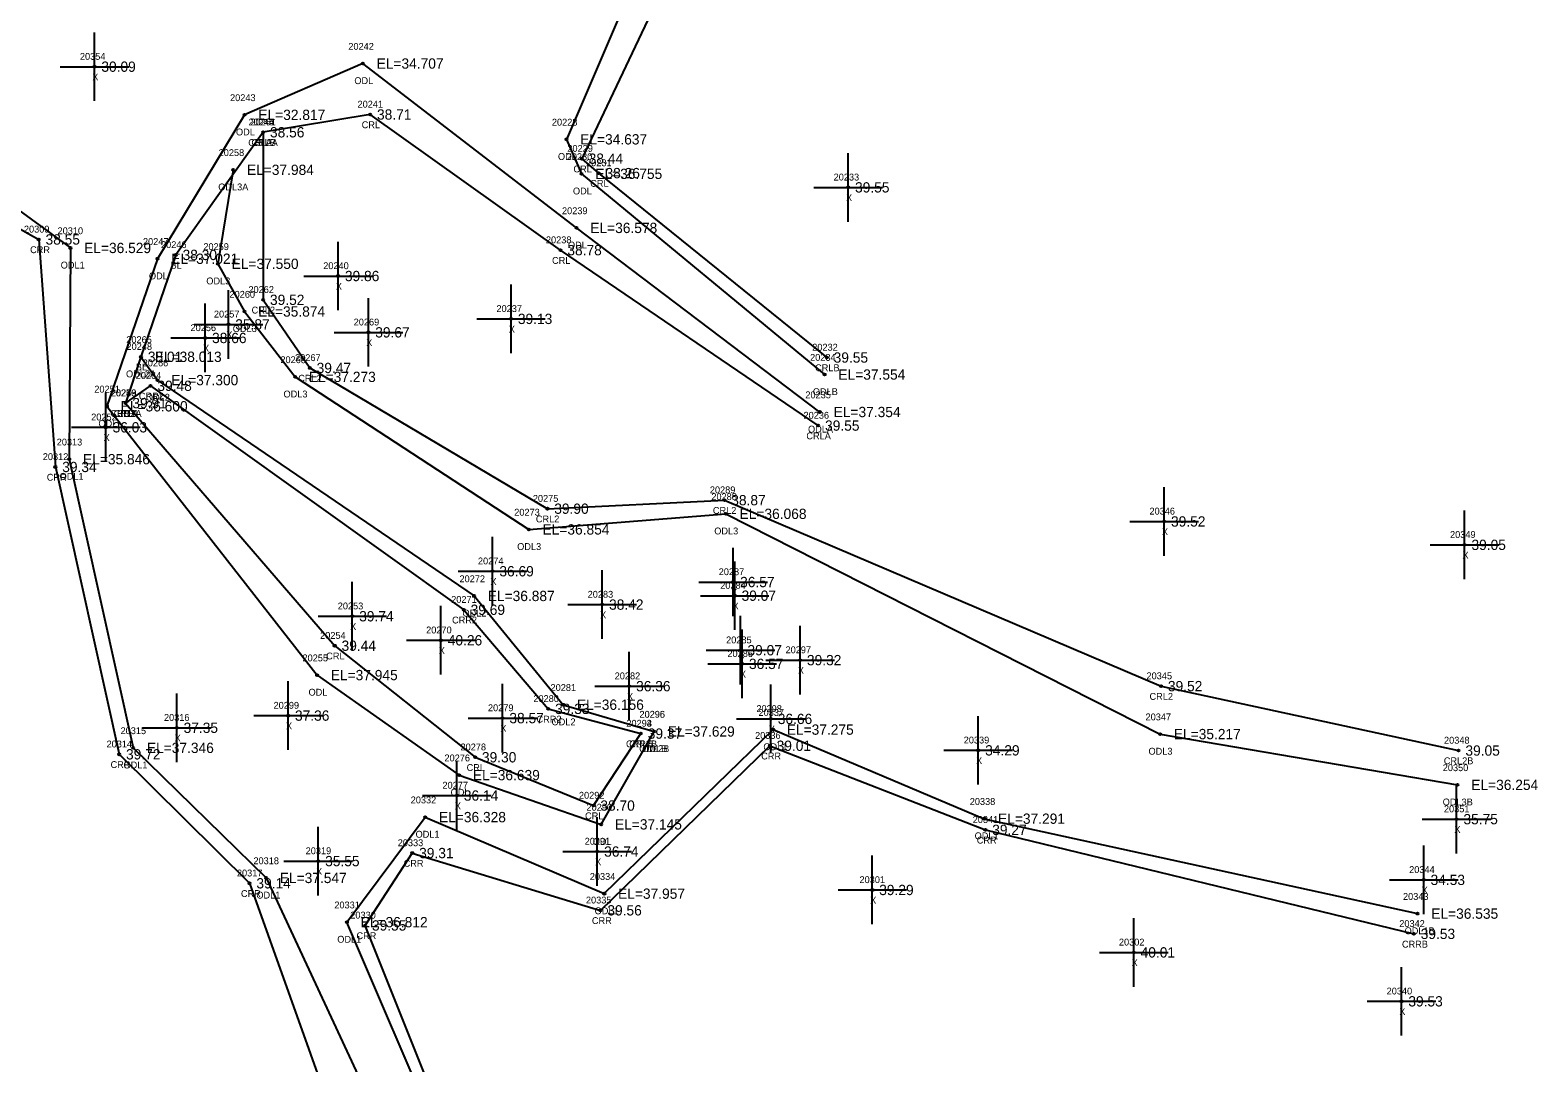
# Model space of a CAD drawing. Extents: x 2619569 to 2620117, y 784503 to 785150.
# Drawn here: x 2619897.7 to 2620117.4, y 784673.4 to 784823.9 of the extents above; entities that cross this region are included whole.
import ezdxf

# ---------------------------------------------------------------- set-up
doc = ezdxf.new("R2010")
doc.units = 0
for name, color, linetype in [('RD_DTM_BkLn1', 7, 'Continuous'), ('RD_DTM_BkLn_txCode', 7, 'Continuous'), ('RD_EX_H2O', 7, 'Continuous'), ('RD_EX_H2O_txCode', 7, 'Continuous'), ('RD_EX_Misc', 7, 'Continuous'), ('RD_EX_Misc_txCode', 7, 'Continuous'), ('RD_EX_TX_H2O_ELEV', 7, 'Continuous'), ('RD_EX_TX_Misc_ELEV', 7, 'Continuous'), ('RD_SMD_Locator', 7, 'Continuous')]:
    doc.layers.add(name, color=color, linetype=linetype)

msp = doc.modelspace()

# ---------------------------------------------------------------- linework, layer by layer
at = {"layer": 'RD_DTM_BkLn1'}
msp.add_lwpolyline([(2619931.64, 784808.99), (2619918.9, 784791.11), (2619913.84, 784776.27), (2619911.58, 784769.51)], dxfattribs=at)
at = {"layer": 'RD_EX_H2O'}
for points in [[(2619849.21, 784838.05), (2619855.06, 784843.73), (2619862.98, 784854.68), (2619876.77, 784858.94), (2619905.89, 784860.53), (2619923.25, 784863.85), (2619948.05, 784872.76), (2619969.08, 784848.67), (2619985.64, 784830.75), (2619975.85, 784807.96), (2619978.05, 784802.93), (2620013.48, 784773.68)], [(2619850.74, 784850.04), (2619858.56, 784858.85), (2619863.71, 784859.84), (2619875.95, 784863.3), (2619903.67, 784868.12), (2619924.46, 784867.36), (2619949.26, 784874.61), (2619971.3, 784850.55), (2619990.94, 784832.2), (2619978.09, 784805.14), (2619980.54, 784803.04), (2620013.79, 784776.16)], [(2620012.79, 784768.22), (2619977.32, 784795.05), (2619946.18, 784819.01), (2619928.94, 784811.53), (2619916.25, 784790.56), (2619908.88, 784769.05), (2619939.5, 784729.88), (2619960.21, 784715.3), (2619980.92, 784708.12), (2619988.62, 784721.66)], [(2619851.94, 784812.36), (2619867.47, 784809.26), (2619885.8, 784805.06), (2619903.55, 784792.13), (2619903.39, 784761.34), (2619912.7, 784719.27), (2619932.07, 784700.31), (2619950.07, 784661.69), (2619964.86, 784626.79)], [(2620012.54, 784766.24), (2619974.98, 784791.81), (2619947.24, 784811.58), (2619931.64, 784808.99)], [(2619931.64, 784808.99), (2619931.64, 784784.57), (2619938.44, 784774.64), (2619973.07, 784754.13), (2619998.87, 784755.37), (2620062.51, 784728.27), (2620105.87, 784718.88)], [(2619858.79, 784802.44), (2619861.97, 784802.62), (2619885.46, 784800.96), (2619898.93, 784793.37), (2619901.36, 784760.21), (2619910.66, 784718.33), (2619929.66, 784699.53), (2619944.47, 784658), (2619963.48, 784625.35)], [(2619927.28, 784803.52), (2619925.05, 784789.82), (2619928.92, 784782.87), (2619936.3, 784773.34), (2619970.36, 784751.11), (2619999.08, 784753.38), (2620062.37, 784721.28), (2620105.72, 784713.88)], [(2619913.84, 784776.27), (2619916.26, 784772.87), (2619962.38, 784741.41), (2619975.37, 784725.56), (2619988.62, 784721.66)], [(2619911.58, 784769.51), (2619915.23, 784772.04), (2619960.88, 784739.4), (2619973.19, 784724.95), (2619986.7, 784721.35)], [(2619911.58, 784769.51), (2619942.07, 784734.16), (2619962.53, 784717.9), (2619979.79, 784710.86), (2619986.7, 784721.35)], [(2619970.99, 784633.29), (2619957.32, 784662.49), (2619943.86, 784693.87), (2619955.27, 784709.18), (2619981.37, 784698.02), (2620005.96, 784721.93), (2620036.75, 784708.95), (2620099.89, 784695.11)], [(2619972.95, 784635.56), (2619958.84, 784662.55), (2619946.5, 784693.39), (2619953.38, 784703.94), (2619980.81, 784695.59), (2620005.48, 784719.58), (2620036.9, 784707.32), (2620099.35, 784692.16)]]:
    msp.add_lwpolyline(points, dxfattribs=at)
at = {"layer": 'RD_EX_Misc'}
for p, q in [((2619907.06, 784813.55), (2619907.06, 784823.55)), ((2619902.06, 784818.55), (2619912.06, 784818.55)), ((2620016.91, 784795.96), (2620016.91, 784805.96)), ((2620011.91, 784800.96), (2620021.91, 784800.96)), ((2619942.56, 784783.04), (2619942.56, 784793.04)), ((2619937.56, 784788.04), (2619947.56, 784788.04)), ((2619967.77, 784776.79), (2619967.77, 784786.79)), ((2619926.58, 784775.99), (2619926.58, 784785.99)), ((2619946.98, 784774.83), (2619946.98, 784784.83)), ((2619923.2, 784774.01), (2619923.2, 784784.01)), ((2619921.58, 784780.99), (2619931.58, 784780.99)), ((2619962.77, 784781.79), (2619972.77, 784781.79)), ((2619918.2, 784779.01), (2619928.2, 784779.01)), ((2619941.98, 784779.83), (2619951.98, 784779.83)), ((2619908.7, 784760.99), (2619908.7, 784770.99)), ((2619903.7, 784765.99), (2619913.7, 784765.99)), ((2620062.96, 784747.27), (2620062.96, 784757.27)), ((2620106.75, 784743.86), (2620106.75, 784753.86)), ((2620057.96, 784752.27), (2620067.96, 784752.27)), ((2619965.07, 784740.01), (2619965.07, 784750.01)), ((2620000.16, 784738.44), (2620000.16, 784748.44)), ((2620101.75, 784748.86), (2620111.75, 784748.86)), ((2619960.07, 784745.01), (2619970.07, 784745.01)), ((2619981.06, 784735.15), (2619981.06, 784745.15)), ((2620000.37, 784736.45), (2620000.37, 784746.45)), ((2619944.64, 784733.45), (2619944.64, 784743.45)), ((2619995.16, 784743.44), (2620005.16, 784743.44)), ((2619995.37, 784741.45), (2620005.37, 784741.45)), ((2619939.64, 784738.45), (2619949.64, 784738.45)), ((2619957.55, 784729.95), (2619957.55, 784739.95)), ((2619976.06, 784740.15), (2619986.06, 784740.15)), ((2620001.23, 784728.5), (2620001.23, 784738.5)), ((2620001.45, 784726.51), (2620001.45, 784736.51)), ((2620009.9, 784727.06), (2620009.9, 784737.06)), ((2619952.55, 784734.95), (2619962.55, 784734.95)), ((2619985, 784723.26), (2619985, 784733.26)), ((2619996.23, 784733.5), (2620006.23, 784733.5)), ((2620004.9, 784732.06), (2620014.9, 784732.06)), ((2619996.45, 784731.51), (2620006.45, 784731.51)), ((2619935.28, 784718.97), (2619935.28, 784728.97)), ((2619966.53, 784718.61), (2619966.53, 784728.61)), ((2619980, 784728.26), (2619990, 784728.26)), ((2620005.65, 784718.49), (2620005.65, 784728.49)), ((2619919.05, 784717.2), (2619919.05, 784727.2)), ((2619930.28, 784723.97), (2619940.28, 784723.97)), ((2619961.53, 784723.61), (2619971.53, 784723.61)), ((2620000.65, 784723.49), (2620010.65, 784723.49)), ((2620035.87, 784713.91), (2620035.87, 784723.91)), ((2619914.05, 784722.2), (2619924.05, 784722.2)), ((2620030.87, 784718.91), (2620040.87, 784718.91)), ((2619959.89, 784707.32), (2619959.89, 784717.32)), ((2619954.89, 784712.32), (2619964.89, 784712.32)), ((2620105.58, 784703.88), (2620105.58, 784713.88)), ((2619939.68, 784697.77), (2619939.68, 784707.77)), ((2619980.34, 784699.16), (2619980.34, 784709.16)), ((2620100.58, 784708.88), (2620110.58, 784708.88)), ((2619975.34, 784704.16), (2619985.34, 784704.16)), ((2620020.43, 784693.56), (2620020.43, 784703.56)), ((2620100.79, 784695.03), (2620100.79, 784705.03)), ((2619934.68, 784702.77), (2619944.68, 784702.77)), ((2620095.79, 784700.03), (2620105.79, 784700.03)), ((2620015.43, 784698.56), (2620025.43, 784698.56)), ((2620058.53, 784684.46), (2620058.53, 784694.46)), ((2620053.53, 784689.46), (2620063.53, 784689.46)), ((2620097.55, 784677.33), (2620097.55, 784687.33)), ((2620092.55, 784682.33), (2620102.55, 784682.33))]:
    msp.add_line(p, q, dxfattribs=at)
at = {"layer": 'RD_SMD_Locator'}
for centre in [(2619907.06, 784818.55), (2619946.18, 784819.01), (2619928.94, 784811.53), (2619947.24, 784811.58), (2619931.64, 784808.99), (2619931.64, 784808.99), (2619931.64, 784808.99), (2619975.85, 784807.96), (2619978.09, 784805.14), (2619927.28, 784803.52), (2619978.05, 784802.93), (2619980.54, 784803.04), (2620016.91, 784800.96), (2619898.93, 784793.37), (2619977.32, 784795.05), (2619903.55, 784792.13), (2619918.9, 784791.11), (2619974.98, 784791.81), (2619916.25, 784790.56), (2619925.05, 784789.82), (2619942.56, 784788.04), (2619931.64, 784784.57), (2619928.92, 784782.87), (2619926.58, 784780.99), (2619967.77, 784781.79), (2619923.2, 784779.01), (2619946.98, 784779.83), (2619913.84, 784776.27), (2619913.84, 784776.27), (2620013.79, 784776.16), (2619938.44, 784774.64), (2620013.48, 784773.68), (2619915.23, 784772.04), (2619916.26, 784772.87), (2619936.3, 784773.34), (2619908.88, 784769.05), (2619911.58, 784769.51), (2619911.58, 784769.51), (2619911.58, 784769.51), (2620012.79, 784768.22), (2619908.7, 784765.99), (2620012.54, 784766.24), (2619901.36, 784760.21), (2619903.39, 784761.34), (2619973.07, 784754.13), (2619998.87, 784755.37), (2619999.08, 784753.38), (2620062.96, 784752.27), (2619970.36, 784751.11), (2620106.75, 784748.86), (2619965.07, 784745.01), (2620000.16, 784743.44), (2619962.38, 784741.41), (2620000.37, 784741.45), (2619944.64, 784738.45), (2619960.88, 784739.4), (2619981.06, 784740.15), (2619942.07, 784734.16), (2619957.55, 784734.95), (2620001.23, 784733.5), (2620009.9, 784732.06), (2619939.5, 784729.88), (2620001.45, 784731.51), (2619985, 784728.26), (2620062.51, 784728.27), (2619975.37, 784725.56), (2619935.28, 784723.97), (2619966.53, 784723.61), (2619973.19, 784724.95), (2620005.65, 784723.49), (2619919.05, 784722.2), (2619986.7, 784721.35), (2619986.7, 784721.35), (2619988.62, 784721.66), (2619988.62, 784721.66), (2620005.96, 784721.93), (2620062.37, 784721.28), (2619912.7, 784719.27), (2620005.48, 784719.58), (2620035.87, 784718.91), (2620105.87, 784718.88), (2619910.66, 784718.33), (2619962.53, 784717.9), (2619960.21, 784715.3), (2619959.89, 784712.32), (2620105.72, 784713.88), (2619979.79, 784710.86), (2619955.27, 784709.18), (2619980.92, 784708.12), (2620036.75, 784708.95), (2620105.58, 784708.88), (2620036.9, 784707.32), (2619953.38, 784703.94), (2619980.34, 784704.16), (2619939.68, 784702.77), (2619929.66, 784699.53), (2619932.07, 784700.31), (2620100.79, 784700.03), (2619981.37, 784698.02), (2620020.43, 784698.56), (2619980.81, 784695.59), (2620099.89, 784695.11), (2619943.86, 784693.87), (2619946.5, 784693.39), (2620099.35, 784692.16), (2620058.53, 784689.46), (2620097.55, 784682.33)]:
    msp.add_circle(centre, 0.15, dxfattribs=at)

# ---------------------------------------------------------------- texts
at = {"layer": 'RD_DTM_BkLn_txCode'}
for s, p in [('20245', (2619929.52, 784809.99)), ('BLA', (2619930.4, 784806.99)), ('20246', (2619916.76, 784792.11)), ('BL', (2619918.15, 784789.11)), ('20248', (2619911.73, 784777.27)), ('BL', (2619913.09, 784774.27)), ('20250', (2619909.42, 784770.51)), ('BLB', (2619910.35, 784767.51))]:
    msp.add_text(s, height=1, dxfattribs=at).set_placement(p)
at = {"layer": 'RD_EX_H2O_txCode'}
for s, p in [('20242', (2619944.06, 784821.01)), ('ODL', (2619944.94, 784816.01)), ('20243', (2619926.82, 784813.53)), ('20241', (2619945.4, 784812.58)), ('20244', (2619929.52, 784809.99)), ('20261', (2619929.78, 784809.99)), ('20228', (2619973.73, 784809.96)), ('ODL', (2619927.69, 784808.53)), ('CRL', (2619946.01, 784809.58)), ('20258', (2619925.16, 784805.52)), ('CRL2A', (2619929.47, 784806.99)), ('CRLB', (2619929.94, 784806.99)), ('20229', (2619975.98, 784806.14)), ('ODL', (2619974.61, 784804.96)), ('20230', (2619975.89, 784804.93)), ('20231', (2619978.71, 784804.04)), ('CRL', (2619976.87, 784803.14)), ('ODL3A', (2619925.1, 784800.52)), ('ODL', (2619976.8, 784799.93)), ('CRL', (2619979.32, 784801.04)), ('20239', (2619975.2, 784797.05)), ('20309', (2619896.78, 784794.37)), ('20310', (2619901.68, 784794.13)), ('20247', (2619914.13, 784792.56)), ('20238', (2619972.86, 784792.81)), ('CRR', (2619897.68, 784791.37)), ('20259', (2619922.93, 784791.82)), ('ODL', (2619976.07, 784792.05)), ('ODL1', (2619902.14, 784789.13)), ('CRL', (2619973.75, 784789.81)), ('ODL', (2619915, 784787.56)), ('ODL3', (2619923.36, 784786.82)), ('20260', (2619926.74, 784784.87)), ('20262', (2619929.5, 784785.57)), ('CRL2', (2619929.96, 784782.57)), ('ODL3', (2619927.22, 784779.87)), ('20265', (2619911.7, 784778.27)), ('20232', (2620011.67, 784777.16)), ('20266', (2619914.09, 784774.87)), ('20268', (2619934.16, 784775.34)), ('20267', (2619936.3, 784775.64)), ('20234', (2620011.36, 784775.68)), ('ODL2A', (2619911.66, 784773.27)), ('20264', (2619913.08, 784773.04)), ('CRL2', (2619936.76, 784772.64)), ('CRLB', (2620012.09, 784774.16)), ('20251', (2619907.04, 784771.05)), ('20263', (2619909.44, 784770.51)), ('20249', (2619909.46, 784770.51)), ('ODL3', (2619934.61, 784770.34)), ('ODLB', (2620011.76, 784770.68)), ('CRR2', (2619913.53, 784770.04)), ('ODL2', (2619914.56, 784769.87)), ('20235', (2620010.67, 784770.22)), ('ODL', (2619907.64, 784766.05)), ('CRR2A', (2619909.39, 784767.51)), ('CRLA', (2619909.86, 784767.51)), ('20236', (2620010.4, 784767.24)), ('CRLA', (2620010.82, 784764.24)), ('ODLA', (2620011.06, 784765.22)), ('20313', (2619901.56, 784763.34)), ('20312', (2619899.53, 784761.21)), ('CRR', (2619900.11, 784758.21)), ('ODL1', (2619901.98, 784758.34)), ('20275', (2619970.95, 784755.13)), ('20289', (2619996.75, 784756.37)), ('20288', (2619996.97, 784755.38)), ('20273', (2619968.24, 784753.11)), ('CRL2', (2619997.19, 784753.37)), ('CRL2', (2619971.39, 784752.13)), ('ODL3', (2619997.39, 784750.38)), ('ODL3', (2619968.67, 784748.11)), ('20272', (2619960.26, 784743.41)), ('20271', (2619959.05, 784740.4)), ('CRR2', (2619959.18, 784737.4)), ('ODL2', (2619960.69, 784738.41)), ('20254', (2619939.95, 784735.16)), ('20255', (2619937.38, 784731.88)), ('CRL', (2619940.84, 784732.16)), ('20345', (2620060.39, 784729.27)), ('ODL', (2619938.26, 784726.88)), ('20281', (2619973.53, 784727.56)), ('20280', (2619971.03, 784725.95)), ('CRL2', (2620060.83, 784726.27)), ('CRR2', (2619971.49, 784722.95)), ('ODL2', (2619973.68, 784722.56)), ('20293', (2619984.58, 784722.35)), ('20294', (2619984.58, 784722.35)), ('20296', (2619986.48, 784723.66)), ('20295', (2619986.5, 784723.66)), ('20337', (2620003.84, 784723.93)), ('20347', (2620060.25, 784723.28)), ('20315', (2619910.86, 784721.27)), ('20336', (2620003.34, 784720.58)), ('20348', (2620103.75, 784719.88)), ('20314', (2619908.82, 784719.33)), ('20278', (2619960.41, 784718.9)), ('CRR2B', (2619984.53, 784719.35)), ('CRLB', (2619985, 784719.35)), ('ODL2B', (2619986.45, 784718.66)), ('ODLB', (2619986.9, 784718.66)), ('ODL1', (2620004.55, 784718.93)), ('ODL3', (2620060.68, 784718.28)), ('CRR', (2619909.41, 784716.33)), ('ODL1', (2619911.29, 784716.27)), ('20276', (2619958.07, 784717.3)), ('CRL', (2619961.3, 784715.9)), ('CRR', (2620004.23, 784717.58)), ('20350', (2620103.57, 784715.88)), ('CRL2B', (2620103.72, 784716.88)), ('20332', (2619953.15, 784711.18)), ('ODL', (2619958.97, 784712.3)), ('20292', (2619977.67, 784711.86)), ('CRL', (2619978.56, 784708.86)), ('20290', (2619978.77, 784710.12)), ('20338', (2620034.63, 784710.95)), ('ODL3B', (2620103.56, 784710.88)), ('20341', (2620035.06, 784708.32)), ('20333', (2619951.26, 784704.94)), ('ODL1', (2619953.86, 784706.18)), ('ODL', (2619979.68, 784705.12)), ('ODL1', (2620035.34, 784705.95)), ('CRR', (2620035.65, 784705.32)), ('20318', (2619930.23, 784702.31)), ('20317', (2619927.82, 784700.53)), ('CRR', (2619952.12, 784701.94)), ('20334', (2619979.25, 784700.02)), ('CRR', (2619928.41, 784697.53)), ('ODL1', (2619930.66, 784697.31)), ('20331', (2619942.02, 784695.87)), ('20335', (2619978.69, 784696.59)), ('20343', (2620097.77, 784697.11)), ('20330', (2619944.34, 784694.39)), ('CRR', (2619979.56, 784693.59)), ('ODL1', (2619979.96, 784695.02)), ('CRR', (2619945.25, 784691.39)), ('20342', (2620097.23, 784693.16)), ('ODL1B', (2620098.01, 784692.11)), ('ODL1', (2619942.45, 784690.87)), ('CRRB', (2620097.62, 784690.16))]:
    msp.add_text(s, height=1, dxfattribs=at).set_placement(p)
at = {"layer": 'RD_EX_Misc_txCode'}
for s, p in [('20354', (2619904.94, 784819.55)), ('X', (2619906.74, 784816.55)), ('20233', (2620014.79, 784801.96)), ('X', (2620016.6, 784798.96)), ('20240', (2619940.4, 784789.04)), ('X', (2619942.24, 784786.04)), ('20257', (2619924.47, 784781.99)), ('20237', (2619965.65, 784782.79)), ('20256', (2619921.06, 784780.01)), ('20269', (2619944.84, 784780.83)), ('X', (2619967.45, 784779.79)), ('X', (2619922.88, 784777.01)), ('X', (2619926.27, 784778.99)), ('X', (2619946.67, 784777.83)), ('20252', (2619906.58, 784766.99)), ('X', (2619908.39, 784763.99)), ('20346', (2620060.82, 784753.27)), ('X', (2620062.64, 784750.27)), ('20349', (2620104.63, 784749.86)), ('X', (2620106.44, 784746.86)), ('20274', (2619962.95, 784746.01)), ('20287', (2619998.04, 784744.44)), ('X', (2619964.76, 784743.01)), ('20284', (2619998.26, 784742.45)), ('20283', (2619978.94, 784741.15)), ('X', (2619999.84, 784741.44)), ('20253', (2619942.52, 784739.45)), ('X', (2619980.75, 784738.15)), ('X', (2620000.06, 784739.45)), ('X', (2619944.32, 784736.45)), ('20270', (2619955.4, 784735.95)), ('20285', (2619999.12, 784734.5)), ('20297', (2620007.78, 784733.06)), ('X', (2619957.24, 784732.95)), ('20286', (2619999.31, 784732.51)), ('X', (2620000.92, 784731.5)), ('20282', (2619982.88, 784729.26)), ('X', (2620001.13, 784729.51)), ('X', (2620009.58, 784730.06)), ('20299', (2619933.16, 784724.97)), ('20279', (2619964.41, 784724.61)), ('X', (2619984.68, 784726.26)), ('20298', (2620003.53, 784724.49)), ('20316', (2619917.19, 784723.2)), ('X', (2619918.74, 784720.2)), ('X', (2619934.97, 784721.97)), ('X', (2619966.21, 784721.61)), ('X', (2620005.33, 784721.49)), ('20339', (2620033.75, 784719.91)), ('X', (2620035.55, 784716.91)), ('20277', (2619957.78, 784713.32)), ('X', (2619959.58, 784710.32)), ('20351', (2620103.74, 784709.88)), ('X', (2620105.26, 784706.88)), ('20291', (2619978.51, 784705.16)), ('20319', (2619937.84, 784703.77)), ('X', (2619939.36, 784700.77)), ('X', (2619980.03, 784702.16)), ('20344', (2620098.67, 784701.03)), ('20301', (2620018.56, 784699.56)), ('X', (2620100.48, 784698.03)), ('X', (2620020.11, 784696.56)), ('20302', (2620056.37, 784690.46)), ('X', (2620058.22, 784687.46)), ('20340', (2620095.39, 784683.33)), ('X', (2620097.23, 784680.33))]:
    msp.add_text(s, height=1, dxfattribs=at).set_placement(p)
at = {"layer": 'RD_EX_TX_H2O_ELEV'}
for s, p in [('EL=34.707', (2619948.18, 784818.26)), ('EL=32.817', (2619930.94, 784810.78)), ('38.71', (2619948.24, 784810.83)), ('38.56', (2619932.64, 784808.24)), ('38.56', (2619932.64, 784808.24)), ('EL=34.637', (2619977.85, 784807.21)), ('38.44', (2619979.09, 784804.39)), ('EL=37.984', (2619929.28, 784802.77)), ('EL=36.755', (2619980.05, 784802.18)), ('38.26', (2619981.54, 784802.29)), ('EL=36.578', (2619979.32, 784794.3)), ('38.55', (2619899.93, 784792.62)), ('EL=36.529', (2619905.55, 784791.38)), ('EL=37.021', (2619918.25, 784789.81)), ('38.78', (2619975.98, 784791.06)), ('EL=37.550', (2619927.05, 784789.07)), ('39.52', (2619932.64, 784783.82)), ('EL=35.874', (2619930.92, 784782.12)), ('EL=38.013', (2619915.84, 784775.52)), ('39.55', (2620014.79, 784775.41)), ('EL=37.300', (2619918.26, 784772.12)), ('EL=37.273', (2619938.3, 784772.59)), ('39.47', (2619939.44, 784773.89)), ('EL=37.554', (2620015.48, 784772.93)), ('39.48', (2619916.23, 784771.29)), ('EL=36.600', (2619910.88, 784768.3)), ('39.91', (2619912.58, 784768.76)), ('39.91', (2619912.58, 784768.76)), ('39.55', (2620013.54, 784765.49)), ('EL=37.354', (2620014.79, 784767.47)), ('39.34', (2619902.36, 784759.46)), ('EL=35.846', (2619905.39, 784760.59)), ('38.87', (2619999.87, 784754.62)), ('39.90', (2619974.07, 784753.38)), ('EL=36.068', (2620001.08, 784752.63)), ('EL=36.854', (2619972.36, 784750.36)), ('EL=36.887', (2619964.38, 784740.66)), ('39.69', (2619961.88, 784738.65)), ('39.44', (2619943.07, 784733.41)), ('EL=37.945', (2619941.5, 784729.13)), ('39.52', (2620063.51, 784727.52)), ('39.33', (2619974.19, 784724.2)), ('EL=36.156', (2619977.37, 784724.81)), ('39.37', (2619987.7, 784720.6)), ('39.37', (2619987.7, 784720.6)), ('EL=37.629', (2619990.62, 784720.91)), ('EL=37.629', (2619990.62, 784720.91)), ('EL=37.275', (2620007.96, 784721.18)), ('EL=35.217', (2620064.37, 784720.53)), ('39.72', (2619911.66, 784717.58)), ('EL=37.346', (2619914.7, 784718.52)), ('39.30', (2619963.53, 784717.15)), ('39.01', (2620006.48, 784718.83)), ('39.05', (2620106.87, 784718.13)), ('EL=36.639', (2619962.21, 784714.55)), ('EL=36.254', (2620107.72, 784713.13)), ('EL=36.328', (2619957.27, 784708.43)), ('38.70', (2619980.79, 784710.11)), ('EL=37.145', (2619982.92, 784707.37)), ('39.27', (2620037.9, 784706.57)), ('EL=37.291', (2620038.75, 784708.2)), ('39.31', (2619954.38, 784703.19)), ('EL=37.547', (2619934.07, 784699.56)), ('39.14', (2619930.66, 784698.78)), ('EL=37.957', (2619983.37, 784697.27)), ('EL=36.812', (2619945.86, 784693.12)), ('39.56', (2619981.81, 784694.84)), ('EL=36.535', (2620101.89, 784694.36)), ('39.55', (2619947.5, 784692.64)), ('39.53', (2620100.35, 784691.41))]:
    msp.add_text(s, height=1.5, dxfattribs=at).set_placement(p)
at = {"layer": 'RD_EX_TX_Misc_ELEV'}
for s, p in [('30.09', (2619908.06, 784817.8)), ('38.56', (2619932.64, 784808.24)), ('39.55', (2620017.91, 784800.21)), ('38.30', (2619919.9, 784790.36)), ('39.86', (2619943.56, 784787.29)), ('39.13', (2619968.77, 784781.04)), ('35.87', (2619927.58, 784780.24)), ('39.67', (2619947.98, 784779.08)), ('38.66', (2619924.2, 784778.26)), ('38.01', (2619914.84, 784775.52)), ('39.91', (2619912.58, 784768.76)), ('36.03', (2619909.7, 784765.24)), ('39.52', (2620063.96, 784751.52)), ('39.05', (2620107.75, 784748.11)), ('36.69', (2619966.07, 784744.26)), ('36.57', (2620001.16, 784742.69)), ('38.42', (2619982.06, 784739.4)), ('39.07', (2620001.37, 784740.7)), ('39.74', (2619945.64, 784737.7)), ('40.26', (2619958.55, 784734.2)), ('39.07', (2620002.23, 784732.75)), ('36.57', (2620002.45, 784730.76)), ('39.32', (2620010.9, 784731.31)), ('36.36', (2619986, 784727.51)), ('37.36', (2619936.28, 784723.22)), ('38.57', (2619967.53, 784722.86)), ('36.66', (2620006.65, 784722.74)), ('37.35', (2619920.05, 784721.45)), ('34.29', (2620036.87, 784718.16)), ('36.14', (2619960.89, 784711.57)), ('35.75', (2620106.58, 784708.13)), ('35.55', (2619940.68, 784702.02)), ('36.74', (2619981.34, 784703.41)), ('39.29', (2620021.43, 784697.81)), ('34.53', (2620101.79, 784699.28)), ('40.01', (2620059.53, 784688.71)), ('39.53', (2620098.55, 784681.58))]:
    msp.add_text(s, height=1.5, dxfattribs=at).set_placement(p)

doc.saveas('drawing.dxf')
